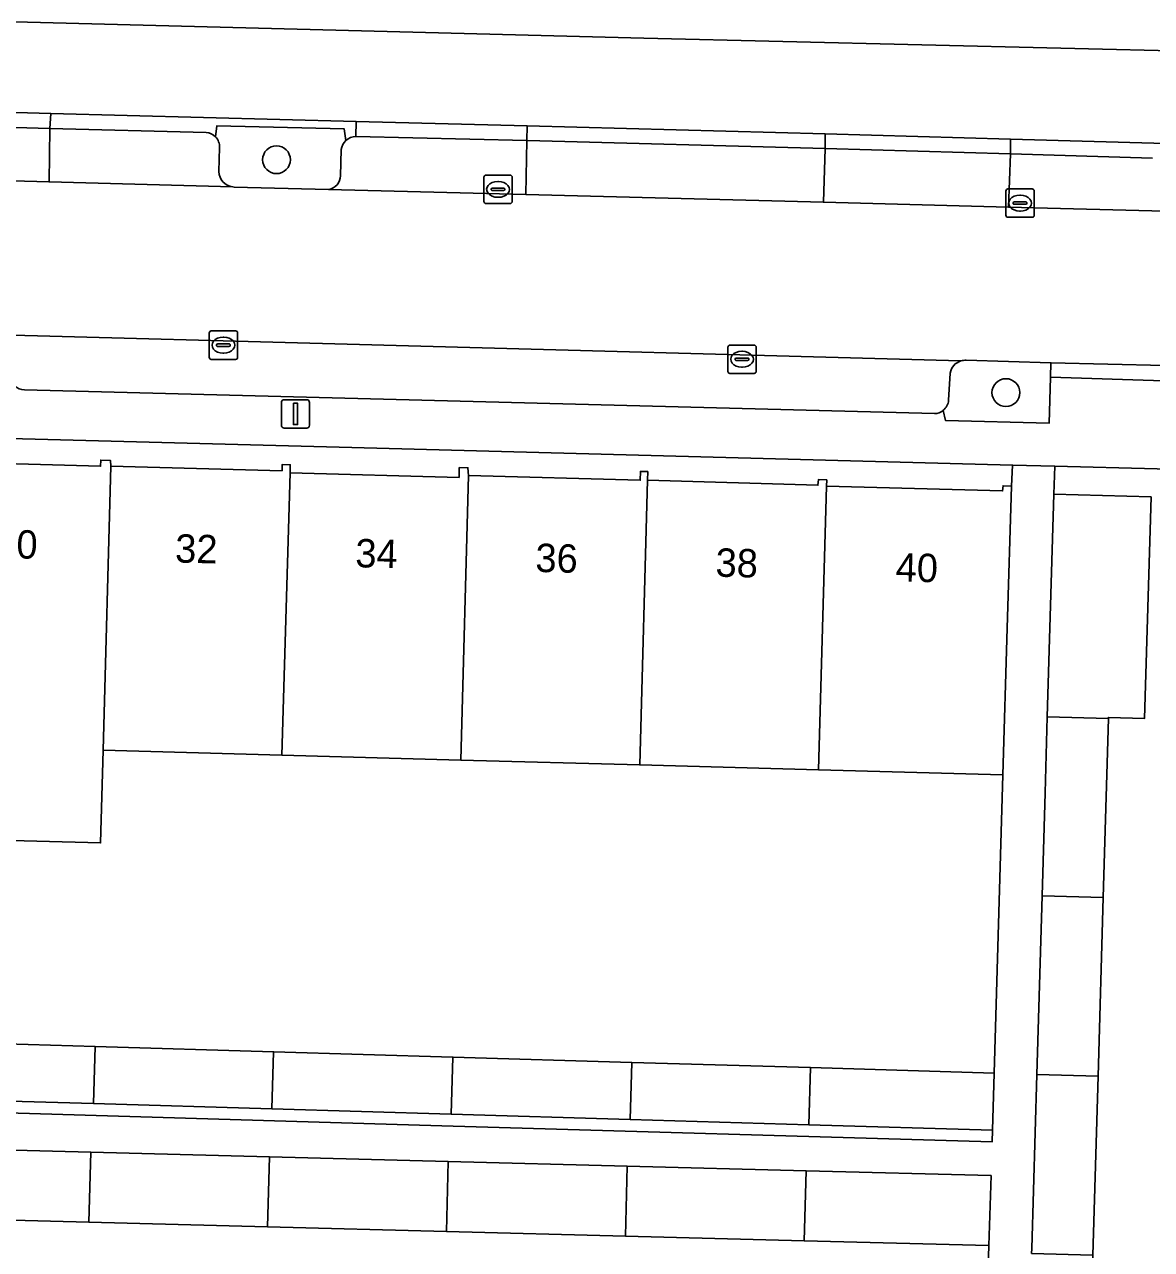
# Model space of a CAD drawing. Extents: x 162082 to 163401, y 388089 to 388636.
# Drawn here: x 162464.07 to 162503.75, y 388429.85 to 388472.98 of the extents above; entities that cross this region are included whole.
import ezdxf

# ---------------------------------------------------------------- set-up
doc = ezdxf.new("R2010")
doc.units = 0
for name, color, linetype in [('IMGEO_Berm_open', 7, 'Continuous'), ('IMGEO_Boom', 7, 'Continuous'), ('IMGEO_Erf', 7, 'Continuous'), ('IMGEO_Fietspad_gesloten', 7, 'Continuous'), ('IMGEO_Groenvoorziening', 7, 'Continuous'), ('IMGEO_Kolk', 7, 'Continuous'), ('IMGEO_Lichtmast', 7, 'Continuous'), ('IMGEO_Pand', 7, 'Continuous'), ('IMGEO_Pand_nummerreeks', 7, 'Continuous'), ('IMGEO_Parkeervlak_open', 7, 'Continuous'), ('IMGEO_Rijbaan_lokaal_gesloten', 7, 'Continuous'), ('IMGEO_Rijbaan_lokaal_open', 7, 'Continuous'), ('IMGEO_Voetpad_open', 7, 'Continuous')]:
    doc.layers.add(name, color=color, linetype=linetype)

msp = doc.modelspace()

# ---------------------------------------------------------------- linework, layer by layer
at = {"layer": 'IMGEO_Berm_open'}
for points in [[(162475.747, 388469.573), (162464.998, 388469.844), (162464.966, 388469.324), (162470.462, 388469.185)], [(162475.732, 388469.036), (162475.747, 388469.573)], [(162470.797, 388469.028), (162470.847, 388469.418), (162475.331, 388469.305), (162475.387, 388468.901)], [(162509.296, 388468.657), (162498.783, 388468.948), (162498.785, 388468.428), (162503.783, 388468.283)]]:
    msp.add_lwpolyline(points, dxfattribs=at)
msp.add_lwpolyline([(162492.263, 388469.129), (162481.767, 388469.41), (162481.757, 388468.898), (162481.782, 388468.897), (162492.262, 388468.617)], close=True, dxfattribs=at)
for centre, radius, start, end in [((162470.422, 388468.663), 0.524, 44.1973, 85.5818), ((162475.738, 388468.513), 0.523, 90.6353, 132.1059)]:
    msp.add_arc(centre, radius, start, end, dxfattribs=at)
at = {"layer": 'IMGEO_Boom'}
for centre in [(162472.943, 388468.221), (162498.621, 388460.024)]:
    msp.add_circle(centre, 0.489, dxfattribs=at)
at = {"layer": 'IMGEO_Erf'}
for points in [[(162460.81, 388457.592), (162466.749, 388457.429), (162466.755, 388457.647), (162467.095, 388457.638), (162467.109, 388457.436), (162473.141, 388457.271), (162473.147, 388457.493), (162473.428, 388457.485), (162473.42, 388457.202), (162479.369, 388457.039), (162479.379, 388457.385), (162479.682, 388457.377), (162479.704, 388457.104), (162485.747, 388456.938), (162485.755, 388457.247), (162486.015, 388457.24), (162486.004, 388456.938), (162492.004, 388456.763), (162492.02, 388456.963), (162492.312, 388456.95), (162492.306, 388456.734), (162498.506, 388456.564), (162498.522, 388456.744), (162498.814, 388456.727), (162498.856, 388457.469), (162475.598, 388458.096), (162435.462, 388459.144)], [(162525.566, 388456.776), (162500.341, 388457.43), (162500.306, 388456.45), (162503.733, 388456.35), (162503.506, 388448.552), (162502.232, 388448.59), (162502.231, 388448.546), (162502.048, 388442.25), (162501.864, 388435.951), (162501.681, 388429.655), (162501.498, 388423.356), (162501.314, 388417.057), (162501.131, 388410.76), (162500.943, 388404.291), (162511.285, 388404.011)], [(162460.26, 388437.185), (162466.557, 388436.999), (162472.838, 388436.814), (162479.152, 388436.628), (162485.448, 388436.442), (162491.738, 388436.257), (162498.205, 388436.066), (162498.518, 388446.563), (162492.029, 388446.741), (162485.732, 388446.913), (162479.434, 388447.086), (162473.136, 388447.258), (162466.839, 388447.431), (162466.751, 388444.167), (162460.453, 388444.34)]]:
    msp.add_lwpolyline(points, dxfattribs=at)
for points in [[(162485.393, 388434.433), (162479.098, 388434.619), (162472.78, 388434.805), (162466.503, 388434.99), (162460.206, 388435.176), (162453.908, 388435.362), (162447.611, 388435.547), (162441.313, 388435.733), (162434.808, 388435.925), (162434.796, 388435.51), (162438.558, 388435.399), (162451.799, 388435.008), (162463.467, 388434.663), (162478.763, 388434.212), (162498.133, 388433.64), (162498.145, 388434.057), (162491.683, 388434.248)], [(162498.026, 388429.993), (162491.522, 388430.163), (162485.225, 388430.327), (162478.928, 388430.491), (162472.629, 388430.655), (162466.332, 388430.819), (162460.033, 388430.984), (162453.734, 388431.129), (162447.437, 388431.315), (162441.14, 388431.501), (162434.899, 388431.639), (162434.704, 388424.236), (162440.931, 388424.059), (162447.229, 388423.88), (162453.526, 388423.702), (162459.824, 388423.523), (162466.122, 388423.345), (162472.419, 388423.166), (162478.717, 388422.987), (162485.014, 388422.809), (162485.111, 388426.243), (162491.408, 388426.064), (162491.312, 388422.63), (162497.803, 388422.446)]]:
    msp.add_lwpolyline(points, close=True, dxfattribs=at)
at = {"layer": 'IMGEO_Fietspad_gesloten'}
for points in [[(162529.917, 388471.443), (162485.874, 388472.504), (162448.342, 388473.476), (162416.648, 388474.331), (162416.648, 388474.82), (162409.151, 388475.063), (162409.128, 388474.536), (162400.452, 388474.693), (162389.858, 388475.046), (162386.763, 388475.096), (162375.068, 388475.331), (162368.942, 388475.51), (162357.381, 388475.853), (162351.02, 388475.969)], [(162358.201, 388472.554), (162369.037, 388472.285), (162375.078, 388472.135), (162386.708, 388471.847), (162390.238, 388471.759), (162401.837, 388471.472), (162408.03, 388471.318), (162408.007, 388470.829), (162416.505, 388470.602), (162416.525, 388471.113), (162420.862, 388471.019), (162440.416, 388470.49), (162440.436, 388470.49), (162448.448, 388470.301), (162458.442, 388470.036), (162464.998, 388469.844), (162475.747, 388469.573), (162481.767, 388469.41), (162492.263, 388469.129), (162498.783, 388468.948), (162509.296, 388468.657)]]:
    msp.add_lwpolyline(points, dxfattribs=at)
at = {"layer": 'IMGEO_Groenvoorziening'}
for points in [[(162475.387, 388468.901), (162475.331, 388469.305), (162470.847, 388469.418), (162470.797, 388469.028)], [(162470.942, 388468.657), (162470.916, 388467.809)], [(162475.2, 388467.66), (162475.221, 388468.578)], [(162471.402, 388467.266), (162471.449, 388467.262), (162474.776, 388467.179)], [(162500.191, 388460.562), (162500.207, 388461.077), (162497.219, 388461.162)], [(162496.414, 388459.399), (162496.5, 388459.037), (162500.139, 388458.942), (162500.191, 388460.562)], [(162496.658, 388460.711), (162496.606, 388459.753)]]:
    msp.add_lwpolyline(points, dxfattribs=at)
for centre, radius, start, end in [((162470.429, 388468.67), 0.513, 358.5214, 44.1732), ((162475.735, 388468.518), 0.518, 132.2734, 173.3264), ((162471.469, 388467.815), 0.553, 180.6441, 263.0148), ((162474.704, 388467.67), 0.496, 278.339, 358.8689), ((162497.198, 388460.615), 0.548, 107.0374, 169.912), ((162497.197, 388460.603), 0.56, 87.7713, 106.6337), ((162496.09, 388459.804), 0.518, 308.6695, 354.3821)]:
    msp.add_arc(centre, radius, start, end, dxfattribs=at)
at = {"layer": 'IMGEO_Kolk'}
for p, q in [((162480.242, 388466.753), (162480.242, 388467.605)), ((162480.317, 388467.679), (162481.169, 388467.679)), ((162480.73, 388467.459), (162480.755, 388467.459)), ((162481.243, 388467.605), (162481.243, 388466.753)), ((162480.501, 388467.173), (162480.501, 388467.185)), ((162480.939, 388467.136), (162480.541, 388467.136)), ((162480.544, 388467.222), (162480.942, 388467.222)), ((162480.985, 388467.185), (162480.985, 388467.173)), ((162498.619, 388466.269), (162498.619, 388467.121)), ((162498.694, 388467.195), (162499.546, 388467.195)), ((162499.107, 388466.975), (162499.132, 388466.975)), ((162499.62, 388467.121), (162499.62, 388466.269)), ((162481.169, 388466.679), (162480.317, 388466.679)), ((162480.753, 388466.899), (162480.728, 388466.899)), ((162498.878, 388466.689), (162498.878, 388466.701)), ((162499.316, 388466.652), (162498.918, 388466.652)), ((162498.921, 388466.738), (162499.319, 388466.738)), ((162499.362, 388466.701), (162499.362, 388466.689)), ((162499.546, 388466.195), (162498.694, 388466.195)), ((162499.13, 388466.415), (162499.105, 388466.415)), ((162470.649, 388462.193), (162471.501, 388462.193)), ((162470.574, 388461.267), (162470.574, 388462.119)), ((162471.062, 388461.973), (162471.087, 388461.973)), ((162471.575, 388462.119), (162471.575, 388461.267)), ((162470.833, 388461.687), (162470.833, 388461.699)), ((162471.271, 388461.65), (162470.873, 388461.65)), ((162470.876, 388461.736), (162471.274, 388461.736)), ((162471.085, 388461.413), (162471.06, 388461.413)), ((162471.317, 388461.699), (162471.317, 388461.687)), ((162488.832, 388460.771), (162488.832, 388461.623)), ((162488.907, 388461.697), (162489.759, 388461.697)), ((162489.32, 388461.477), (162489.345, 388461.477)), ((162489.833, 388461.623), (162489.833, 388460.771)), ((162471.501, 388461.193), (162470.649, 388461.193)), ((162489.091, 388461.191), (162489.091, 388461.203)), ((162489.529, 388461.154), (162489.131, 388461.154)), ((162489.134, 388461.24), (162489.532, 388461.24)), ((162489.343, 388460.917), (162489.318, 388460.917)), ((162489.575, 388461.203), (162489.575, 388461.191)), ((162489.759, 388460.697), (162488.907, 388460.697))]:
    msp.add_line(p, q, dxfattribs=at)
for points in [[(162480.242, 388466.753), (162480.242, 388467.605)], [(162480.317, 388467.679), (162481.169, 388467.679)], [(162481.243, 388467.605), (162481.243, 388466.753)], [(162498.619, 388466.269), (162498.619, 388467.121)], [(162498.694, 388467.195), (162499.546, 388467.195)], [(162499.62, 388467.121), (162499.62, 388466.269)], [(162481.169, 388466.679), (162480.317, 388466.679)], [(162499.546, 388466.195), (162498.694, 388466.195)], [(162470.649, 388462.193), (162471.501, 388462.193)], [(162470.574, 388461.267), (162470.574, 388462.119)], [(162471.575, 388462.119), (162471.575, 388461.267)], [(162488.832, 388460.771), (162488.832, 388461.623)], [(162488.907, 388461.697), (162489.759, 388461.697)], [(162489.833, 388461.623), (162489.833, 388460.771)], [(162471.501, 388461.193), (162470.649, 388461.193)], [(162489.759, 388460.697), (162488.907, 388460.697)]]:
    msp.add_lwpolyline(points, dxfattribs=at)
for centre, radius, start, end in [((162480.319, 388467.603), 0.0765, 91.552, 178.448), ((162480.319, 388467.603), 0.0765, 91.552, 178.448), ((162481.167, 388467.603), 0.0765, 1.552, 88.448), ((162481.167, 388467.603), 0.0765, 1.552, 88.448), ((162480.541, 388467.182), 0.0403, 85.8775, 175.7526), ((162480.538, 388467.172), 0.0366, 178.938, 274.7102), ((162480.942, 388467.179), 0.043, 264.8664, 352.4533), ((162480.946, 388467.184), 0.0386, 1.7309, 96.639), ((162498.696, 388467.119), 0.0765, 91.552, 178.448), ((162498.696, 388467.119), 0.0765, 91.552, 178.448), ((162499.544, 388467.119), 0.0765, 1.552, 88.448), ((162499.544, 388467.119), 0.0765, 1.552, 88.448), ((162480.319, 388466.755), 0.0765, 181.552, 268.448), ((162480.319, 388466.755), 0.0765, 181.552, 268.448), ((162481.167, 388466.755), 0.0765, 271.552, 358.448), ((162481.167, 388466.755), 0.0765, 271.552, 358.448), ((162498.918, 388466.698), 0.0403, 85.8775, 175.7526), ((162498.915, 388466.688), 0.0366, 178.938, 274.7102), ((162499.319, 388466.695), 0.043, 264.8664, 352.4533), ((162499.323, 388466.7), 0.0386, 1.7309, 96.639), ((162498.696, 388466.271), 0.0765, 181.552, 268.448), ((162498.696, 388466.271), 0.0765, 181.552, 268.448), ((162499.544, 388466.271), 0.0765, 271.552, 358.448), ((162499.544, 388466.271), 0.0765, 271.552, 358.448), ((162470.651, 388462.117), 0.0765, 91.552, 178.448), ((162470.651, 388462.117), 0.0765, 91.552, 178.448), ((162471.499, 388462.117), 0.0765, 1.552, 88.448), ((162471.499, 388462.117), 0.0765, 1.552, 88.448), ((162470.873, 388461.696), 0.0403, 85.8775, 175.7526), ((162470.87, 388461.686), 0.0366, 178.938, 274.7102), ((162471.274, 388461.693), 0.043, 264.8664, 352.4533), ((162471.278, 388461.698), 0.0386, 1.7309, 96.639), ((162488.909, 388461.621), 0.0765, 91.552, 178.448), ((162488.909, 388461.621), 0.0765, 91.552, 178.448), ((162489.757, 388461.621), 0.0765, 1.552, 88.448), ((162489.757, 388461.621), 0.0765, 1.552, 88.448), ((162470.651, 388461.269), 0.0765, 181.552, 268.448), ((162470.651, 388461.269), 0.0765, 181.552, 268.448), ((162471.499, 388461.269), 0.0765, 271.552, 358.448), ((162471.499, 388461.269), 0.0765, 271.552, 358.448), ((162489.131, 388461.2), 0.0403, 85.8775, 175.7526), ((162489.128, 388461.19), 0.0366, 178.938, 274.7102), ((162489.532, 388461.197), 0.043, 264.8664, 352.4533), ((162489.536, 388461.202), 0.0386, 1.7309, 96.639), ((162488.909, 388460.773), 0.0765, 181.552, 268.448), ((162488.909, 388460.773), 0.0765, 181.552, 268.448), ((162489.757, 388460.773), 0.0765, 271.552, 358.448), ((162489.757, 388460.773), 0.0765, 271.552, 358.448)]:
    msp.add_arc(centre, radius, start, end, dxfattribs=at)
for centre, major_axis, ratio, start_param, end_param in [((162480.729, 388467.179), (-0.387, 0.002), 0.722429, 4.712389, 7.853982), ((162480.754, 388467.179), (-0.39, 0.002), 0.717154, 1.570796, 4.712389), ((162499.106, 388466.695), (-0.387, 0.002), 0.722429, 4.712389, 7.853982), ((162499.131, 388466.695), (-0.39, 0.002), 0.717154, 1.570796, 4.712389), ((162471.061, 388461.693), (-0.387, 0.002), 0.722429, 4.712389, 7.853982), ((162471.086, 388461.693), (-0.39, 0.002), 0.717154, 1.570796, 4.712389), ((162489.319, 388461.197), (-0.387, 0.002), 0.722429, 4.712389, 7.853982), ((162489.344, 388461.197), (-0.39, 0.002), 0.717154, 1.570796, 4.712389)]:
    msp.add_ellipse(centre, major_axis=major_axis, ratio=ratio, start_param=start_param, end_param=end_param, dxfattribs=at)
at = {"layer": 'IMGEO_Lichtmast'}
for p, q in [((162473.116, 388458.874), (162473.116, 388459.674)), ((162473.116, 388459.674), (162473.116, 388458.874)), ((162473.216, 388459.774), (162474.006, 388459.774)), ((162474.006, 388459.774), (162473.216, 388459.774)), ((162474.106, 388459.674), (162474.106, 388458.874)), ((162474.106, 388458.874), (162474.106, 388459.674)), ((162474.006, 388458.774), (162473.216, 388458.774)), ((162473.216, 388458.774), (162474.006, 388458.774))]:
    msp.add_line(p, q, dxfattribs=at)
msp.add_lwpolyline([(162473.536, 388459.649), (162473.686, 388459.649), (162473.686, 388458.899), (162473.536, 388458.899), (162473.536, 388459.649)], dxfattribs=at)
for centre, start, end in [((162473.216, 388459.674), 90, 180), ((162473.216, 388459.674), 90, 180), ((162474.006, 388459.674), 0, 90), ((162474.006, 388459.674), 360, 90), ((162473.216, 388458.874), 180, 270), ((162473.216, 388458.874), 180, 270), ((162474.006, 388458.874), 270, 0), ((162474.006, 388458.874), 270, 0)]:
    msp.add_arc(centre, 0.1, start, end, dxfattribs=at)
at = {"layer": 'IMGEO_Pand'}
for points in [[(162467.109, 388457.436), (162467.095, 388457.638), (162466.755, 388457.647), (162466.749, 388457.429), (162460.81, 388457.592), (162460.541, 388447.603), (162460.453, 388444.34), (162466.751, 388444.167), (162466.839, 388447.431)], [(162466.839, 388447.431), (162473.136, 388447.258), (162473.42, 388457.202), (162473.428, 388457.485), (162473.147, 388457.493), (162473.141, 388457.271), (162467.109, 388457.436)], [(162473.136, 388447.258), (162479.434, 388447.086), (162479.704, 388457.104), (162479.682, 388457.377), (162479.379, 388457.385), (162479.369, 388457.039), (162473.42, 388457.202)], [(162479.704, 388457.104), (162479.434, 388447.086), (162485.732, 388446.913), (162486.004, 388456.938), (162486.015, 388457.24), (162485.755, 388457.247), (162485.747, 388456.938)], [(162492.029, 388446.741), (162492.306, 388456.734), (162492.312, 388456.95), (162492.02, 388456.963), (162492.004, 388456.763), (162486.004, 388456.938), (162485.732, 388446.913)], [(162492.029, 388446.741), (162498.518, 388446.563), (162498.668, 388451.73), (162498.814, 388456.727), (162498.522, 388456.744), (162498.506, 388456.564), (162492.306, 388456.734)], [(162500.078, 388448.607), (162502.231, 388448.546), (162502.232, 388448.59), (162503.506, 388448.552), (162503.733, 388456.35), (162500.306, 388456.45)], [(162500.078, 388448.607), (162500, 388445.936), (162499.894, 388442.31), (162502.048, 388442.25), (162502.231, 388448.546)], [(162501.864, 388435.951), (162502.048, 388442.25), (162499.894, 388442.31), (162499.711, 388436.012)], [(162460.26, 388437.185), (162460.206, 388435.176), (162466.503, 388434.99), (162466.557, 388436.999)], [(162466.557, 388436.999), (162466.503, 388434.99), (162472.78, 388434.805), (162472.838, 388436.814)], [(162479.098, 388434.619), (162479.152, 388436.628), (162472.838, 388436.814), (162472.78, 388434.805)], [(162485.448, 388436.442), (162479.152, 388436.628), (162479.098, 388434.619), (162485.393, 388434.433)], [(162485.448, 388436.442), (162485.393, 388434.433), (162491.683, 388434.248), (162491.738, 388436.257)], [(162491.738, 388436.257), (162491.683, 388434.248), (162498.145, 388434.057), (162498.205, 388436.066)], [(162501.864, 388435.951), (162499.711, 388436.012), (162499.533, 388429.895), (162499.528, 388429.715), (162501.681, 388429.655)], [(162466.402, 388433.282), (162460.103, 388433.446), (162460.033, 388430.984), (162466.332, 388430.819)], [(162472.699, 388433.118), (162466.402, 388433.282), (162466.332, 388430.819), (162472.629, 388430.655)], [(162478.983, 388432.954), (162472.699, 388433.118), (162472.629, 388430.655), (162478.928, 388430.491)], [(162485.294, 388432.789), (162478.983, 388432.954), (162478.928, 388430.491), (162485.225, 388430.327)], [(162491.591, 388432.625), (162485.294, 388432.789), (162485.225, 388430.327), (162491.522, 388430.163)], [(162491.591, 388432.625), (162491.522, 388430.163), (162498.026, 388429.993), (162498.098, 388432.455)]]:
    msp.add_lwpolyline(points, close=True, dxfattribs=at)
at = {"layer": 'IMGEO_Parkeervlak_open'}
for points in [[(162470.462, 388469.185), (162464.966, 388469.324), (162464.938, 388467.441), (162471.402, 388467.266)], [(162470.916, 388467.809), (162470.942, 388468.657)], [(162503.783, 388468.283), (162498.785, 388468.428), (162498.717, 388466.552), (162504.674, 388466.396)], [(162497.037, 388461.139), (162475.436, 388461.725), (162463.206, 388462.062)], [(162496.606, 388459.753), (162496.658, 388460.711)], [(162464.072, 388460.121), (162496.103, 388459.284)]]:
    msp.add_lwpolyline(points, dxfattribs=at)
msp.add_lwpolyline([(162492.262, 388468.617), (162481.782, 388468.897), (162481.757, 388468.898), (162481.721, 388466.997), (162492.196, 388466.723)], close=True, dxfattribs=at)
for centre, radius, start, end in [((162470.422, 388468.663), 0.524, 44.1973, 85.5818), ((162470.429, 388468.67), 0.513, 358.5214, 44.1732), ((162471.469, 388467.815), 0.553, 180.6441, 263.0148), ((162497.198, 388460.615), 0.548, 107.0374, 169.912), ((162464.072, 388460.592), 0.471, 222.9605, 270.0424), ((162496.09, 388459.804), 0.518, 308.6695, 354.3821), ((162496.088, 388459.802), 0.519, 271.6509, 308.9354)]:
    msp.add_arc(centre, radius, start, end, dxfattribs=at)
at = {"layer": 'IMGEO_Rijbaan_lokaal_gesloten'}
for points in [[(162504.674, 388466.396), (162498.717, 388466.552), (162492.196, 388466.723), (162481.721, 388466.997), (162474.776, 388467.179), (162471.449, 388467.262), (162471.402, 388467.266), (162464.938, 388467.441), (162458.384, 388467.618), (162448.429, 388467.886), (162439.373, 388468.131), (162439.33, 388468.131), (162438.401, 388468.167), (162419.774, 388468.618), (162418.749, 388468.644), (162408.223, 388468.89), (162403.702, 388469.023), (162402.728, 388469.034), (162390.18, 388469.346), (162386.66, 388469.431), (162375.01, 388469.723), (162368.972, 388469.873), (162357.12, 388470.167), (162357.479, 388464.187)], [(162497.219, 388461.162), (162500.207, 388461.077), (162504.218, 388460.977), (162504.932, 388460.949), (162506.169, 388460.922), (162506.201, 388460.918), (162506.233, 388460.913), (162520.169, 388460.539), (162523.795, 388460.454), (162524.35, 388460.445), (162524.419, 388465.848)], [(162363.947, 388464.619), (162365.328, 388464.563), (162365.948, 388464.538), (162370.967, 388464.412), (162371.659, 388464.386), (162390.127, 388463.916), (162391.354, 388463.895), (162408.184, 388463.445), (162420.621, 388463.13), (162421.807, 388463.11), (162462.126, 388462.081), (162463.206, 388462.062), (162475.436, 388461.725), (162497.037, 388461.139)]]:
    msp.add_lwpolyline(points, dxfattribs=at)
msp.add_arc((162497.197, 388460.603), 0.56, 87.7713, 106.6337, dxfattribs=at)
at = {"layer": 'IMGEO_Rijbaan_lokaal_open'}
for points in [[(162464.998, 388469.844), (162458.442, 388470.036), (162458.448, 388469.509), (162464.966, 388469.324)], [(162464.966, 388469.324), (162458.448, 388469.509), (162458.384, 388467.618), (162464.938, 388467.441)], [(162481.767, 388469.41), (162475.747, 388469.573), (162475.732, 388469.036), (162481.757, 388468.898)], [(162498.783, 388468.948), (162492.263, 388469.129), (162492.262, 388468.617), (162498.785, 388468.428)], [(162498.785, 388468.428), (162492.262, 388468.617), (162492.196, 388466.723), (162498.717, 388466.552)]]:
    msp.add_lwpolyline(points, close=True, dxfattribs=at)
for points in [[(162474.776, 388467.179), (162481.721, 388466.997), (162481.757, 388468.898)], [(162481.757, 388468.898), (162475.732, 388469.036)], [(162475.221, 388468.578), (162475.2, 388467.66)]]:
    msp.add_lwpolyline(points, dxfattribs=at)
for centre, radius, start, end in [((162475.735, 388468.518), 0.518, 132.2734, 173.3264), ((162475.738, 388468.513), 0.523, 90.6353, 132.1059), ((162474.704, 388467.67), 0.496, 278.339, 358.8689)]:
    msp.add_arc(centre, radius, start, end, dxfattribs=at)
at = {"layer": 'IMGEO_Voetpad_open'}
for points in [[(162342.186, 388475.127), (162342.269, 388477.93), (162351.102, 388477.707), (162351.02, 388475.969), (162357.381, 388475.853), (162357.407, 388477.479), (162368.979, 388477.237), (162368.942, 388475.51), (162375.068, 388475.331), (162375.087, 388477.102), (162386.752, 388476.785), (162386.763, 388475.096), (162389.858, 388475.046), (162389.902, 388476.672), (162400.467, 388476.399), (162400.452, 388474.693), (162409.128, 388474.536), (162409.151, 388475.063), (162416.648, 388474.82), (162416.648, 388474.331), (162448.342, 388473.476), (162485.874, 388472.504), (162529.917, 388471.443)], [(162506.233, 388460.913), (162506.201, 388460.918), (162506.169, 388460.922), (162504.932, 388460.949), (162504.218, 388460.977), (162504.181, 388460.432), (162500.191, 388460.562), (162500.139, 388458.942), (162496.5, 388459.037), (162496.414, 388459.399)], [(162348.465, 388460.809), (162349.16, 388459.748), (162344.51, 388456.617), (162345.699, 388455.235), (162350.246, 388458.32), (162358.756, 388460.74), (162365.975, 388460.578), (162366.001, 388460.726), (162370.521, 388460.602), (162370.546, 388460.711), (162370.655, 388460.714), (162370.734, 388460.717), (162370.734, 388460.784), (162383.691, 388460.456), (162433.966, 388459.183), (162434.894, 388459.159), (162435.462, 388459.144), (162475.598, 388458.096), (162498.856, 388457.469), (162500.341, 388457.43), (162525.566, 388456.776)], [(162496.103, 388459.284), (162464.072, 388460.121)], [(162499.528, 388429.715), (162499.533, 388429.895), (162499.711, 388436.012), (162499.894, 388442.31), (162500, 388445.936), (162500.078, 388448.607), (162500.306, 388456.45), (162500.341, 388457.43), (162498.856, 388457.469), (162498.814, 388456.727), (162498.668, 388451.73), (162498.518, 388446.563), (162498.205, 388436.066), (162498.145, 388434.057), (162498.133, 388433.64), (162478.763, 388434.212), (162463.467, 388434.663)], [(162434.704, 388424.236), (162434.899, 388431.639), (162434.964, 388434.102), (162441.207, 388433.939), (162447.506, 388433.775), (162453.803, 388433.611), (162460.103, 388433.446), (162466.402, 388433.282), (162472.699, 388433.118), (162478.983, 388432.954), (162485.294, 388432.789), (162491.591, 388432.625), (162498.098, 388432.455), (162498.026, 388429.993), (162497.803, 388422.446)]]:
    msp.add_lwpolyline(points, dxfattribs=at)
msp.add_lwpolyline([(162504.218, 388460.977), (162500.207, 388461.077), (162500.191, 388460.562), (162504.181, 388460.432)], close=True, dxfattribs=at)
for centre, radius, start, end in [((162464.072, 388460.592), 0.471, 222.9605, 270.0424), ((162496.088, 388459.802), 0.519, 271.6509, 308.9354)]:
    msp.add_arc(centre, radius, start, end, dxfattribs=at)

# ---------------------------------------------------------------- texts
at = {"layer": 'IMGEO_Pand_nummerreeks'}
for s, rotation, p in [('30', 358.5046, (162463.034, 388454.207)), ('32', 358.5059, (162469.367, 388454.043)), ('34', 358.5059, (162475.71, 388453.877)), ('36', 358.5059, (162482.049, 388453.712)), ('38', 358.5059, (162488.391, 388453.546)), ('40', 358.5059, (162494.731, 388453.38))]:
    msp.add_text(s, height=1, rotation=rotation, dxfattribs=at).set_placement(p)

doc.saveas('drawing.dxf')
